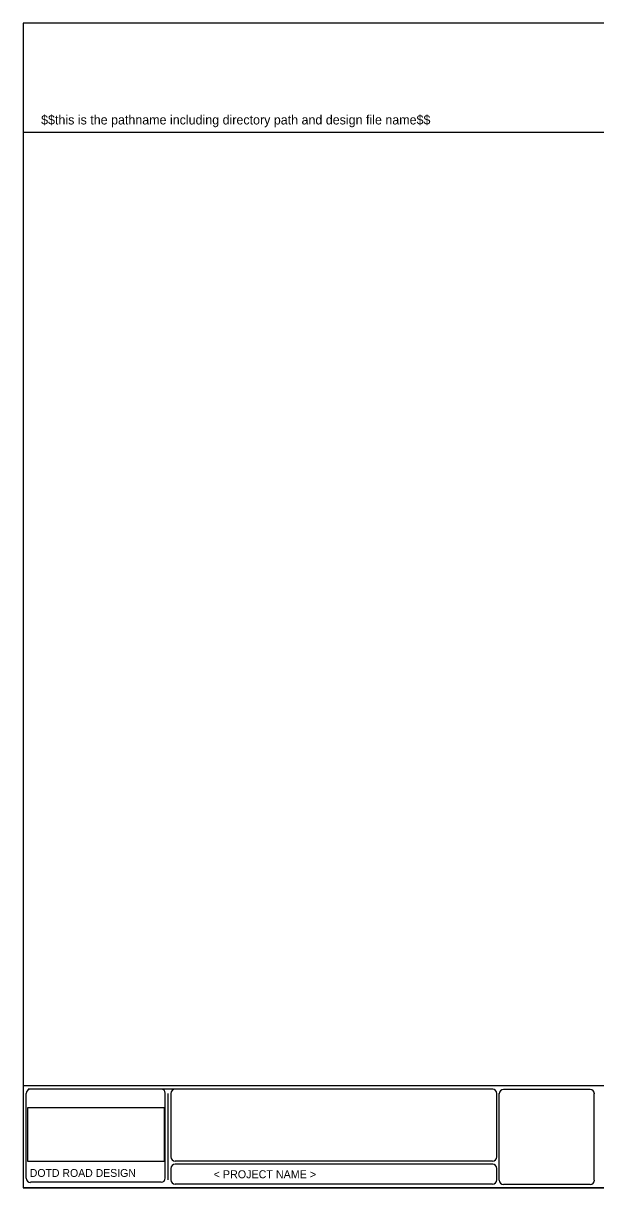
# Model space of a CAD drawing. Extents: x 0 to 1.75, y 0 to 1.33.
# Drawn here: x 0 to 0.655, y 0 to 1.333 of the extents above; entities that cross this region are included whole.
import ezdxf

# ---------------------------------------------------------------- set-up
doc = ezdxf.new("R2010")
doc.units = 0
for name, color, linetype in [('Default', 7, 'Continuous'), ('Plot Border', 7, 'Continuous'), ('Seal', 7, 'Continuous'), ('Sheet Border', 7, 'Continuous')]:
    doc.layers.add(name, color=color, linetype=linetype)

msp = doc.modelspace()

# ---------------------------------------------------------------- linework, layer by layer
at = {"layer": 'Default'}
for p, q in [((0.1744, 0.1129), (0.0056, 0.1129)), ((0.1647, 0.1129), (0.1647, 0.1129))]:
    msp.add_line(p, q, dxfattribs=at)
at = {"layer": 'Plot Border'}
msp.add_lwpolyline([(1.75, 0), (1.75, 1.3333), (0, 1.3333), (0, 0)], close=True, dxfattribs=at)
at = {"layer": 'Seal'}
msp.add_lwpolyline([(0.0047, 0.0303), (0.1618, 0.0303), (0.1618, 0.0915), (0.0047, 0.0915)], close=True, dxfattribs=at)
at = {"layer": 'Sheet Border'}
for p, q in [((0, 1.2083), (0, 0)), ((1.75, 1.2083), (0, 1.2083)), ((1.75, 0.1167), (0, 0.1167)), ((0.0032, 0.0109), (0.0032, 0.108)), ((0.1577, 0.113), (0.0081, 0.113)), ((0.1626, 0.0111), (0.1626, 0.1082)), ((0.1659, 0.0089), (0.1659, 0.108)), ((0.1691, 0.0353), (0.1691, 0.1079)), ((0.5374, 0.1129), (0.1744, 0.1129)), ((0.5374, 0.1129), (0.1744, 0.1129)), ((0.542, 0.0353), (0.542, 0.1079)), ((0.5448, 0.0086), (0.5448, 0.1077)), ((0.6488, 0.1126), (0.5497, 0.1126)), ((0.6537, 0.0086), (0.6537, 0.1077)), ((0.537, 0.0303), (0.174, 0.0303)), ((0.5374, 0.027), (0.1744, 0.027)), ((0.1691, 0.0088), (0.1691, 0.0221)), ((0.542, 0.0088), (0.542, 0.0221)), ((1.75, 0), (0, 0)), ((0.1577, 0.0062), (0.0081, 0.0062)), ((0.537, 0.0039), (0.174, 0.0039)), ((0.6488, 0.0036), (0.5497, 0.0036))]:
    msp.add_line(p, q, dxfattribs=at)
for centre, radius, start, end in [((0.0081, 0.108), 0.00485, 90, 180), ((0.1577, 0.1081), 0.00485, 360, 90), ((0.174, 0.1079), 0.00495, 90, 180), ((0.537, 0.1079), 0.00495, 360, 90), ((0.5497, 0.1076), 0.00495, 90, 180), ((0.6488, 0.1076), 0.00495, 360, 90), ((0.174, 0.0353), 0.00495, 180, 270), ((0.174, 0.0221), 0.00495, 90, 180), ((0.537, 0.0353), 0.00495, 270, 360), ((0.537, 0.0221), 0.00495, 360, 90), ((0.0081, 0.0109), 0.00485, 180, 270), ((0.1577, 0.0111), 0.00485, 270, 360), ((0.174, 0.0089), 0.00495, 180, 270), ((0.537, 0.0089), 0.00495, 270, 360), ((0.5497, 0.0086), 0.00495, 180, 270), ((0.6488, 0.0086), 0.00495, 270, 360)]:
    msp.add_arc(centre, radius, start, end, dxfattribs=at)

# ---------------------------------------------------------------- texts
at = {"layer": 'Plot Border'}
msp.add_text('$$this is the pathname including directory path and design file name$$', height=0.010667, rotation=360, dxfattribs=at).set_placement((0.0204, 1.2175))
at = {"layer": 'Sheet Border'}
for s, height, p in [(' DOTD ROAD DESIGN', 0.008983, (0.0041, 0.0124)), ('               < PROJECT NAME >               ', 0.009167, (0.1669, 0.0108))]:
    msp.add_text(s, height=height, rotation=360, dxfattribs=at).set_placement(p)

doc.saveas('drawing.dxf')
